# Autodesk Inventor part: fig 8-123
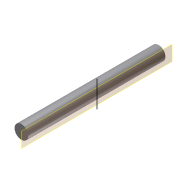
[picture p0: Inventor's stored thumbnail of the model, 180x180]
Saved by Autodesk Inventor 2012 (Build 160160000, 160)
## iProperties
Created: 2007-02
Part Number: fig 8-123
Document SubType Name: Modeling
Designer: Administrator
Density: 1 g/cm^3
Material: Default
Author: Administrator
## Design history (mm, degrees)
node "Sketch1"
sketch "Sketch2"
  geometry: C1 r 5 at (0, 0); 1 further point
  constraints: 1 centre point, 1 coincident, 1 other
  dimensions: "d0" = 10 diameter of C1
extrude "Extrusion1" new body sketch "Sketch2" stored distance "d1" = 100; taper "d2" = 0 deg
workplane "Work Plane1"
sketch "Sketch3"
  geometry: L1 (0, 11)-(0, -8)
  constraints: 2 end point, 1 vertical
body "Solid1"
